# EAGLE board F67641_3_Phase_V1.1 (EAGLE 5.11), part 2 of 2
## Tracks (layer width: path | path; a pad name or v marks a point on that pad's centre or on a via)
ACT  (via drill 0.4)
  Top 0.254: U4.51 117.99,127.26 108.5,136.75 108.5,154.25 100.25,162.5 v59.73,162.5 LED_ACT.K
  Top 0.61: R72.1 v20,160 | JP12.1 34.73,184.77 35,184.5 v35,163.25
  Bottom 0.254: v59.73,162.5 59.73,162.52 59,163.25
  Bottom 0.61: 59,163.25 v35,163.25 33.25,163.25 28.5,158.5 21.5,158.5 v20,160
AUXVCC1  (via drill 0.4)
  Top 0.254: U4.19 115,82.25 116,81.25 116,77.5 116.5,77
  Top 0.406: C5.1 117.25,75.4
  Top 0.61: 116.5,77 C4.1 C5.1 | v117.75,74.25 117.25,74.75 117.25,75.4 | v134.5,74.25 137,76.75 144.69,76.75 JP16.1
  Bottom 0.61: v117.75,74.25 C63.VCC | C63.VCC 131.42,74.25 | C63.VCC v134.5,74.25
AUXVCC2  (via drill 0.4)
  Top 0.254: U4.18 114.49,82.01 115,81.5 115,75.6 C6.1
  Top 0.61: C6.1 C7.1 115.1,72.9 v116.25,71.75 | JP16.3 138,74.25 v135.5,71.75
  Bottom 0.61: v116.25,71.75 v135.5,71.75
AUXVCC3  (via drill 0.4)
  Top 0.254: U4.26 121.01,85.51 v121.5,86 124,86
  Bottom 0.61: v121.5,86 123.25,86 125.5,88.25 133,88.25 133.75,87.5 133.75,82.5 150,66.25 JP15.2
AVCC  (via drill 0.2, 0.6)
  Top 0.254: U4.9 109.99,81.51 110.5,81 110.5,79 111,78.5 111.6,78.5 C31.1 C29.1
  Top 0.406: v85,68.5 D46.C | v85,59 D48.C | v85,78 D44.C
  Top 0.61: D28.C 93.2,31.7 v91.5,30 | D30.C 98.8,31.7 v100.5,30 | D6.C 113.2,31.7 v111.5,30 | D8.C 118.8,31.7 v120.5,30 | D16.C 133.2,31.7 v131.5,30 | D33.C 138.8,31.7 v140.5,30 144,30 145,31 145,50.5 137.5,58 123,58 120,61 113.5,61 112,62.5 112,71 111.5,71.5 111.5,76.75 C29.1 | v85,68.5 R123.1 | v85,78 R117.1 | v85,59 R127.1
  Top 0.813: v91.5,30 88,30 87,31 87,55.5 85,57.5 v85,59 | v85,86 85,87.65 R36.2
  Bottom 0.813: v91.5,30 v100.5,30 v111.5,30 v120.5,30 v131.5,30 v140.5,30 | v85,59 v85,68.5 v85,78 v85,86
BTN1  (via drill 0.2)
  Top 0.406: 132,182 JP1.1 | R49.2 131.4,146.16 BTN1.2
  Top 0.61: v132,163.5 132,182 | v132,158 132,147.26 BTN1.2
  Bottom 0.61: v132,158 v132,163.5
BTN1/RF_VREG_EN  (via drill 0.2)
  Top 0.254: 122.5,146.5 122.5,102.25 124.5,100.25 124.5,94 v124.75,93.75 | U4.37 121.01,90.99 122.25,89.75 v122.25,89.5
  Top 0.61: v129.5,160.5 122.5,153.5 122.5,146.5 | v129.5,166 JP1.2
  Bottom 0.254: v124.75,93.75 124.75,92 v122.25,89.5
  Bottom 0.61: v129.5,160.5 v129.5,166
BTN2  (via drill 0.2)
  Top 0.254: R50.2 125,122 123,120 123,102.5 125,100.5 125,95 v125.5,94.5 | U4.36 120.74,90.51 121.5,89.75 v121.5,89
  Top 0.406: R50.2 131.4,126.05 BTN2.2
  Bottom 0.254: v125.5,94.5 125.5,92 123,89.5 123,89.25 122.5,88.75 121.75,88.75 v121.5,89
COM0  (via drill 0.2)
  Top 0.254: U4.32 116.5,88.5 111.25,93.75 v111.25,94.75
  Bottom 0.254: LCD1.COM0 94.74,150.5 106.5,150.5 113,144 113,96.75 111.25,95 v111.25,94.75
COM1  (via drill 0.2)
  Top 0.254: U4.33 119.61,89 116.75,89 112,93.75 v112,94
  Bottom 0.254: LCD1.COM1 96.78,151 106.75,151 113.5,144.25 113.5,96.5 112,95 v112,94
COM2  (via drill 0.2)
  Top 0.254: U4.34 117,89.5 112.75,93.75 v112.75,94.75
  Bottom 0.254: LCD1.COM2 98.82,151.5 107,151.5 114,144.5 114,96.25 112.75,95 v112.75,94.75
COM3  (via drill 0.2)
  Top 0.254: U4.35 117.25,90 113.5,93.75 v113.5,94
  Bottom 0.254: LCD1.COM3 100.86,152 105.5,152 107.23,152.02 114.5,144.75 114.5,96 113.5,95 v113.5,94
CUR1+
  Top 0.61: 95.25,34.5 95.25,30.75 93.5,29 I1+.TP | 95.25,34.5 95.25,37 | 95.25,37 95.25,40.75 93.95,42.05 TVS2.C 94,43.05 94,44.5 94.45,44.95 R/L9.2 | 95.25,34.5 D3.A | 95.25,37 D11.C
CUR1+1
  Top 0.61: 115.25,34.5 115.25,30.75 113.5,29 I2+.TP | 115.25,34.5 115.25,37 | 115.25,37 115.25,40.75 113.95,42.05 TVS1.C 114,43.05 114,44.5 114.45,44.95 R/L1.2 | 115.25,37 D2.C | 115.25,34.5 D1.A
CUR1+2
  Top 0.61: 135.25,34.5 135.25,30.75 133.5,29 I3+.TP | 135.25,34.5 135.25,37 | 135.25,37 135.25,40.75 133.95,42.05 TVS3.C 134,43.05 134,44.5 134.45,44.95 R/L3.2 | 135.25,37 D14.C | 135.25,34.5 D13.A
CUR1-
  Top 0.61: 96.75,34.5 96.75,30.75 98.5,29 I1-.TP | 96.75,34.5 96.75,37 | 96.75,37 96.75,40.75 98.05,42.05 TVS2.A 98,43.05 98,44.5 97.55,44.95 R/L10.2 | 96.75,37 D12.C | 96.75,34.5 D4.A
CUR1-1
  Top 0.61: 116.75,34.5 116.75,30.75 118.5,29 I2-.TP | 116.75,34.5 116.75,37 | 116.75,37 116.75,40.75 118.05,42.05 TVS1.A 118,43.05 118,44.5 117.55,44.95 R/L2.2 | 116.75,34.5 D5.A | 116.75,37 D10.C
CUR1-2
  Top 0.61: 136.75,34.5 136.75,30.75 138.5,29 I3-.TP | 136.75,34.5 136.75,37 | 136.75,37 136.75,40.75 138.05,42.05 TVS3.A 138,43.05 138,44.5 137.55,44.95 R/L4.2 | 136.75,34.5 D15.A | 136.75,37 D35.C
DB9_+12V
  Top 0.406: D26.1 D25.1 19.88,142.53 22.43,142.53 C55.+ 22.5,137 | R63.2 22.71,134.41 | R63.2 22.5,137 | U1.8 28.09,134.41 26.53,134.41 26.25,134.12 22.52,134.12 R63.2 | Q1.E 22.4,134.2 R63.2 | 22.5,137 C54.2
DB9_-12V  (via drill 0.6)
  Top 0.406: v21.25,140 D24.2 19.7,137.05 C54.1 R67.1 | U1.5 26.66,138.16 26.25,137.75 25.1,137.75 R66.2 25,140 | 25,140 C56.- | v26.5,140 25,140
  Bottom 0.406: v21.25,140 v26.5,140
DB9_GND  (via drill 0.6)
  Top 0.406: U2.3 26.89,143.37 26.5,143.75 26.5,145 26.1,145.4 C56.+ 23.75,145.4 | 23.75,145.4 C55.- | v12,147.5 D27.2 | v23.75,147.38 23.75,145.4
  Bottom 0.406: RS1.G1 6.75,150.5 6.62,150.38
  Bottom 0.61: 2.5,143.5 2.61,143.61 RS1.5 8.18,143.68 v12,147.5 12,150 13,151 21.62,151 23.75,148.88 v23.75,147.38
  Bottom 1.016: RS1.G2 2.5,129.85 2.5,143.5 2.5,146.25 6.62,150.38 6.86,150.61 6.86,150.64
DRESET  (via drill 0.2)
  Top 0.254: U4.100 v107,85.5
  Bottom 0.254: v107,85.5 107,89.5 110,92.5 119.5,92.5 126,99 133.25,99 134.5,100.25 134.5,105.75 136,107.25 138.75,107.25 139.95,108.45 JP5.2
DTCK  (via drill 0.2)
  Top 0.254: U4.99 106.49,85.99 106.75,86.25 v107.75,86.25
  Bottom 0.254: v107.75,86.25 107.75,89.25 110.5,92 119.75,92 126.25,98.5 133.5,98.5 135,100 135,103.5 136,104.5 138.5,104.5 JP6.2
DTDI  (via drill 0.2)
  Top 0.254: U4.97 106,87 106.75,87.75 v109.25,87.75
  Bottom 0.254: v109.25,87.75 109.25,88.75 111.5,91 120.25,91 126.75,97.5 134,97.5 136,99.5 138.5,99.5 139.86,100.86 JP8.2
DTDO  (via drill 0.2)
  Top 0.254: U4.96 105.76,87.51 106.75,88.5 v110,88.5
  Bottom 0.254: v110,88.5 112,90.5 120.5,90.5 127,97 138.5,97 139.82,98.32 JP9.2
DTMS  (via drill 0.2)
  Top 0.254: U4.98 106.25,86.5 106.75,87 v108.5,87
  Bottom 0.254: v108.5,87 108.5,89 111,91.5 120,91.5 126.5,98 133.75,98 135.5,99.75 135.5,101.5 136,102 138.5,102 139.9,103.4 JP7.2
DVCC  (via drill 0.2, 0.4, 0.6)
  Top 0.254: U4.21 115.99,82.76 117.75,81 119.75,81 120.25,80.5 120.25,78.9 C16.1 C17.1 | R41.2 138.4,86.5 | C41.2 143.53,79.38 | IC1.8 141.4,80.38 141.5,80.28 | C51.1 113.5,142.15 R47.1 113.53,144.62 IRDA.P$1 118.62,144.62 118.75,144.75
  Top 0.406: 138.4,86.5 143,86.5 144,85.5 144,80.1 C41.2 142.28,79.5 141.5,80.28 R40.2 | v61,155.5 R58.1 | v71,155.5 R22.1 | v81,155.5 R57.1 | v91,155.5 R21.1 | v101,155.5 R20.1 | v121.25,144.75 118.75,144.75 | JP17.6 118.21,179.04 118.25,179 118.25,168.75 | 117,167.5 118.25,168.75 | 119.5,167.5 118.25,168.75 | 118.25,168.25 118.5,168 | 118.25,168.75 118.25,168.25 | 118.25,168.25 118,168
  Top 0.508: RF1.9 67.97,176.53 68.35,176.15 R79.1
  Top 0.61: R79.1 C59.2 68.35,171 C58.+ 68.6,170.6 68.5,170.5 68.5,168.5 | OPTO2.1 13.98,159.02 17.5,155.5 25.75,155.5 | 43,135.5 R65.1 | 44,136.5 43,135.5 | 44,134.5 43,135.5 | v44,155.5 25.75,155.5 | 67.5,167.5 68.5,168.5 | 69.5,167.5 68.5,168.5 | U2.8 36.2,145.91 R70.2 R71.1 C57.1 39.9,145.85 40,145.75 43,145.75 | 43,145.75 44,144.75 | 44,146.75 43,145.75 | 43,145.75 43.75,145.75 44,145.5 | R19.2 88.15,93.65 88.25,93.75 v88.25,95 | C17.1 120.65,75.85 121.5,75 128,75 135.5,82.5 135.5,86.5 | R51.1 133,95 132.75,94.75 | 135.5,92 135.5,86.5 | R41.2 135.65,86.35 135.5,86.5 | 140.5,142 v139.5,142 R49.1 | 142,143.5 140.5,142 | 142,140.5 140.5,142 | 141,142 141.5,142.5 | 140.5,142 141,142 | 141,142 141.75,141.25 | R50.1 138,122 138.12,121.88 | OPTO1.1 22.23,159.02 25.75,155.5
  Top 0.813: DVCC.1 DVCC.2 154,135.25 154,132.75 DVCC.3 DVCC.4 | R36.1 84.99,94.26 v83.5,95.75
  Top 1.27: JP3.2 73.08,107.92 70,111 55,111 44,122 44,134.5 44,136.5 44,144.75 44,145.5 44,146.75 v44,155.5 56,167.5 67.5,167.5 69.5,167.5 117,167.5 119.5,167.5 125,167.5 142,150.5 142,143.5 142,140.5 142,135 | 142,133 142,135 | 142,133 142,125.75 138.12,121.88 125,108.75 125,102.5 132.75,94.75 135.5,92 142.46,92 JP10.2 | 154,135.25 153.75,135.25 152.5,134 | 154,132.75 153.75,132.75 152.75,133.75 | 152.5,134 152.75,133.75 | 143,134 152.5,134 | 142,135 143,134 | 142,133 143,134 | 152.75,133.75 153.25,133.75 153.75,134.25
  Bottom 0.406: v121.25,144.75 124,142 v139.5,142
  Bottom 0.61: v101,155.5 v91,155.5 v81,155.5 v71,155.5 v61,155.5 v44,155.5 | v88.25,95 87.5,95.75 v83.5,95.75
  Bottom 0.813: JP3.2 73.08,95 73.83,95.75 v83.5,95.75
EXT
  Top 0.813: JP10.3
  Top 1.016: JTAG.4 147.28,95.78 146,94.5 JP10.3
GND  (via drill 0.3, 0.4)
  Top 0.254: v56.5,100 56.5,99.5 U3.9 60.65,99.5 C61.2
  Top 0.406: C61.2 C60.2
  Top 0.61: R44.1 51.5,110 | U2.5 34.41,142.09 35,141.5 36.5,141.5
  Top 0.813: C42.2 65.67,89.35 C101.-
  Top 1.016: D17.A 6,108.5 10,104.5 16.5,104.5 | 16.5,104.5 19,104.5 | 19.5,104.5 28.5,104.5 | 29.5,104.5 31.5,104.5 | 31.5,104.5 34,104.5 36.5,102 36.5,101.96 C102.- 40.96,97.5 | 30,106 31.5,104.5 | 30,106 D21.A | 28.5,104.5 30,106 | 28.5,104.5 29.5,104.5 | 29.5,104.5 30,105 | 16.5,104.5 18,106 | 18,106 D19.A | 18,106 19.5,104.5 | 19,104.5 19.5,104.5 | 19,104.5 18,105.5 | ZD3.A 76,87.95 76.45,87.95 76.5,88 80.5,88 | U$1.VO- 73.85,83.15 74,83 80.5,83
  Top 1.27: L6.2 82,36.5
  Bottom 1.016: C101.- 67.39,89.52 U$1.VO-
  other vias: 125.25,83.25 129,85.25 129,81.25 105,100 84.5,139 72,139 59.5,139 74,171 84.5,132 72,132 59.5,132 102,101.5 106,95.5 106,93.5 108,97.5 119,84.5 119.75,84.5 109,85.75 110.25,87 116,48.5 116,50.5 116,46.5 136,46.5 136,48.5 136,50.5 96,46.5 96,48.5 96,50.5 106,46.5 106,48.5 106,50.5 106,52.5 101,43 103.5,43 106,44.5 108.5,43 111,43 126,46.5 126,48.5 126,50.5 126,52.5 121,43 123.5,43 126,44.5 128.5,43 131,43 141,43 143.5,43 88.5,43 91,43 110,97.5 81,38 81,40 81,42 81,44 81,46 81,48 83,38 83,40 83,42 83,44 83,46 83,48 85,38 85,40 85,42 85,44 85,46 85,48 41,150.5 41,153.5 38,153.5 38,150.5 42,144 42,137.5 42,139.5 42,142 55.5,100 55.5,99 56.5,99 56.5,98 55.5,98 46.5,95 47.5,95 48.5,95 46.5,94 47.5,94 48.5,94 63.25,89.25 62.25,89.25 61.25,89.25 140.25,149.5 140.25,148 140.25,146 140.25,144.5 41,129 41,132 38,132 38,129 89,169.5 89,171.5 86,171.5 86,169.5 94.5,165.5 91.5,165.5
  pour Top: 79.5,108 79.5,36 155.5,36 155.75,169.5 142.5,169.5 142.5,186.5 36,186.5 36,124.5 53,108
  pour Bottom: 79.5,108 79.5,36 155.5,36 155.5,66.5 155.75,169.5 142.5,169.5 142.5,186.5 36,186.5 36,124.5 53,108
  pour Top (no thermals): 53.5,93.5 53.5,95 55,95 55,100.5 54,101.5 54,104.5 57,104.5 57,96.5 58,96.5 58,95.5 57,95.5 57,93.5
  pour Top (no thermals): 41.5,98.75 42.75,97.5 49,97.5 49,95 53.5,95 53.5,93.5 43,93.5 39.5,97 39.5,98 40.25,98.75
  pour Top (no thermals): 64,91.5 57.5,91.5 57,92 57,93.5 43,93.5 44.5,92 52.5,92 56,88.5 64,88.5
  pour Bottom (no thermals): 39.5,98 40.25,98.75 41.5,98.75 42.75,97.5 52,97.5 55,100.5 57,100.5 57,99.75 57.5,99.25 62.5,99.25 64,100.75 64,108 79.5,108 79.5,96.5 58,96.5 57,95.5 57,92 57.5,91.5 64,91.5 64,88.5 56,88.5 52.5,92 44.5,92 39.5,97
I1+_IN
  Top 0.254: U4.1 106.01,74.01 103,71 103,70.5
  Top 0.61: R26.2 94.35,52.4 C19.1 C23.1 97.55,54.55 103,60 103,70.5
I1-_IN
  Top 0.254: U4.2 106.49,72.99 104.5,71 104.5,70.5
  Top 0.61: R27.2 99.45,48.6 C20.1 C23.2 99.45,54.2 104.5,59.25 104.5,70.5
I2+_IN
  Top 0.254: U4.3 107,72 106,71 106,70.5
  Top 0.61: R6.2 114.35,52.4 C2.1 C10.1 117.55,53.95 116.5,55 110.25,55 106,59.25 106,70.5
I2-_IN
  Top 0.254: U4.4 107.5,70.5
  Top 0.61: R7.2 119.35,50.4 C3.1 C10.2 119.45,54.3 117.25,56.5 111,56.5 107.5,60 107.5,70.5
I3+_IN
  Top 0.254: U4.5 108.01,71.99 109,71 109,70.5
  Top 0.61: 137.5,52.5 C11.1 134.35,52.4 R9.2 | 137.5,52.5 C13.1 | 137.5,52.5 137.5,54 136.5,55 121,55 118,58 111.75,58 109,60.75 109,70.5
I3-_IN
  Top 0.254: U4.6 108.5,72.5 110.5,70.5
  Top 0.61: R10.2 139.45,48.6 C12.1 C13.2 139.25,52.7 139.25,54.25 137,56.5 122,56.5 119,59.5 112.5,59.5 110.5,61.5 110.5,70.5
INT
  Top 1.016: JTAG.2 148.24,93.24 144.43,89.43 JP10.1
IR_RXD  (via drill 0.2)
  Top 0.254: U4.27 116.01,85.99 v115.26,86.74 | v120.75,133.25 121.5,132.5 121.5,101.75 123.5,99.75 123.5,93.75 123.25,93.5 v123.25,92.25 | v120.75,146.5 118.39,146.5 IRDA.P$3
  Bottom 0.254: v115.26,86.74 115.25,87.25 115.25,89 116.25,90 120.75,90 123,92.25 v123.25,92.25 | v120.75,133.25 120.5,133.5 120.5,146.25 v120.75,146.5
IR_SD  (via drill 0.2)
  Top 0.254: U4.47 121.25,96 122,96.75 122,99 120,101 120,129 v119.25,129.75 | v120.5,147.5 118.39,147.5 IRDA.P$4
  Bottom 0.254: v119.25,129.75 120.5,131 120.5,132.5 120,133 120,147 v120.5,147.5
IR_TXD  (via drill 0.2)
  Top 0.254: v124,93 124,100 122,102 122,145 121.42,145.57 IRDA.P$2 | U4.28 116.5,86.5 v116.25,86.75
  Bottom 0.254: v116.25,86.75 116,87 116,88.75 116.75,89.5 121,89.5 123,91.5 123.5,91.5 124,92 v124,93
LED_PHASE_1  (via drill 0.2)
  Top 0.254: U4.40 117.51,92.49 v116,94
  Bottom 0.254: v116,94 116,146 99,163 70.25,163 68.02,160.77 LED_PHASE_1.K
LED_PHASE_2  (via drill 0.2)
  Top 0.254: U4.30 115.99,87.51 110,93.5 110,95.25 110.75,96 114,96 115,95 v115,94
  Bottom 0.254: LED_PHASE_2.K 78.02,160.77 79.75,162.5 98.75,162.5 115.5,145.75 115.5,95 115,94.5 v115,94
LED_PHASE_3  (via drill 0.2)
  Top 0.254: U4.31 116.25,88 110.5,93.75 110.5,95 111,95.5 113.5,95.5 v114.25,94.75
  Bottom 0.254: LED_PHASE_3.K 88.02,160.77 89.25,162 98.5,162 115,145.5 115,95.5 v114.25,94.75
LINE_1
  Top 0.813: L1.1 6.92,34.77 R1.2
  Top 1.016: LINE_1.TP 16,18 7,27 7,32.57 R1.2
  Bottom 1.016: R1.2 6.92,40.58 7,63 C39.1
LINE_2
  Top 0.813: L3.1 34.92,34.77 R2.2
  Top 1.016: LINE_2.TP 32,29.73 R2.2
  Bottom 1.016: C46.1 20,47.57 R2.2
LINE_3
  Top 0.813: L5.1 62.92,34.77 R3.2
  Top 1.016: LINE_3.TP 48,17.73 R3.2
  Bottom 1.016: R3.2 56.35,32.65 32,57 C50.1 33.36,65.37 U$1.L
LINE_V1
  Top 0.406: D45.C 85,82 D44.A
  Top 0.813: R101.1 8.65,48.65 15,55 70.5,55 78,62.5 78,76 84,82 85,82 R119.2 | R119.2 R118.2 | R119.2 R116.1
LINE_V2
  Top 0.406: D46.A 85,72.5 D47.C
  Top 0.813: R108.1 36.65,48.65 41,53 71.25,53 80,61.75 80,68.5 84,72.5 85,72.5 R122.2 | R122.2 R121.2 | R122.2 R120.1
LINE_V3
  Top 0.406: D49.C 85,63 D48.A
  Top 0.813: R115.1 64.65,48.65 67,51 72,51 84,63 85,63 R126.2 | R126.2 R125.2 | R126.2 R124.1
N$1
  Top 0.813: U$1.26 43.27,86.31 C100.-
N$2
  Top 0.813: U$1.22 53.44,86.61 C100.+
N$3
  Top 0.61: OPTO2.4 ACT.2
N$4
  Top 0.254: U4.29 121.15,87 C49.1
N$5
  Top 0.254: R20.2 97.4,157.38 LED_REACT.A
N$6
  Top 0.254: R21.2 87.15,157.38 LED_PHASE_3.A
N$7
  Top 0.254: R22.2 67.15,157.38 LED_PHASE_1.A
N$8
  Top 0.61: R6.1 R5.2 112.65,46.6 R/L1.1
N$9
  Top 0.254: U1.2 36.78,135.62 R65.2
N$10
  Top 0.254: JP4.1 138.68,109.75 144.53,109.75 145.06,109.22 R48.2
N$11
  Top 0.61: OPTO2.3 ACT.1
N$12
  Top 0.61: R72.2 16.65,163.06 OPTO2.2
N$13
  Top 0.61: D6.A D1.C
N$14
  Top 0.61: D8.A D5.C
N$15
  Top 0.61: D2.A D7.C
N$16
  Top 0.61: D10.A D9.C
N$17
  Top 0.254: U3.5 53.82,96.17 R38.2
N$18
  Bottom 1.016: D17.C 7.8,97.62 R92.2 8.2,97.62 D18.A
N$19
  Top 0.61: R9.1 R8.2 132.65,46.6 R/L3.1
N$20
  Top 0.61: D28.A D3.C
N$21
  Top 0.61: D16.A D13.C
N$22
  Top 0.254: R69.2 35.75,140 36.5,139.25 37.6,139.25 Q2.B
N$23
  Top 0.61: D11.A D29.C
N$24
  Top 0.406: RS1.2 9.55,136.75 9.8,137 R67.2 15.75,137.35 R64.1
N$25
  Top 0.61: D33.A D15.C
N$26
  Top 0.406: U1.6 29.61,136.88 30,136.5 30,133.5 30,133 29.5,132.5 R62.1
N$27
  Top 0.61: D14.A D32.C
N$28
  Top 0.406: R62.2 22.6,132.5 R63.1 20.45,132.4 Q1.B
N$29
  Top 0.61: D35.A D34.C
N$30
  Bottom 0.254: JP17.2 124.19,179.23 JP1.3
N$32
  Top 0.61: R/L9.1 92.55,48.4 R24.2 R26.1
N$33
  Top 0.406: D37.C 154.2,63.66 JP15.1
N$34
  Top 0.406: D37.A 150.8,59.7 152.21,58.29 HD1.2
N$35
  Top 0.254: RF2.3 97.67,172.72 R74.2
N$37
  Top 0.254: U3.4 52.5,98.5 52,98 C45.1
N$38
  Top 0.254: U3.3 52.25,99 51.25,98 50.35,98 R35.1
  Top 0.406: R37.2 R35.1
N$39
  Top 0.61: D30.A D4.C
N$40
  Top 0.61: D12.A D31.C
N$41
  Top 0.406: Q1.C 15.9,133.25 R64.2
N$43
  Top 0.406: U1.7 26.64,135.62 26.25,136 25.15,136 R66.1
N$44
  Top 0.254: R58.2 57.15,157.38 LED_ACT.A
N$45
  Top 0.254: RF2.5 97.78,174 R76.2
N$46
  Top 0.254: R57.2 77.15,157.38 LED_PHASE_2.A
N$47
  Bottom 1.016: D19.C 19.8,97.62 R93.2 20.2,97.62 D20.A
N$48
  Top 0.254: IRDA.P$5 113.53,148.43 C52.1
  Top 0.3: R47.2 C52.1
N$50
  Top 0.254: R79.2 RF1.7
N$51
  Top 0.254: R73.1 60.99,172.75 RF1.4
N$52
  Top 0.254: RF1.15 66.62,180.34 R87.2
N$53
  Top 0.254: RF1.6 58.48,174 R77.1
N$55
  Top 0.254: RF2.10 88.01,176.53 R83.1
N$56
  Top 0.254: R84.1 91.44,177.75 RF2.12
N$57
  Top 0.254: R85.1 91.45,179.12 RF2.14
N$58
  Top 0.406: 20.17,148.16 D27.1 20.1,147.9 R78.1 28.75,149.75 30,148.5 30,145 29.64,144.63 U2.2
N$59
  Top 0.254: RF2.16 88,180.34 R86.1
N$60
  Top 0.254: RF2.18 88.11,181.62 R88.1
N$61
  Top 0.254: R91.1 89.39,183.25 89.79,182.85 91.47,182.85 RF2.20
N$65
  Top 0.61: OPTO1.4 REACT.2
N$67  (via drill 0.6)
  Top 0.406: v16,149.75 R78.2 | D24.1 10.06,140 RS1.3
  Bottom 0.406: RS1.3 8.18,138.18 10,140 14,140 16,142 v16,149.75
N$68
  Top 0.61: OPTO1.3 REACT.1
N$69
  Top 0.406: D26.2 4,145 2.5,143.5 2.5,138.25 4,136.75 RS1.7
N$71
  Top 0.406: D25.2 9.81,142.5 RS1.4
N$72
  Top 0.61: R68.2 24.9,163.06 OPTO1.2
N$78
  Top 0.254: U3.1 53.25,100 53,100.25 C47.1
N$79
  Top 0.254: U1.3 34.88,136.88 35.3,137.3 Q2.E
N$80  (via drill 0.4)
  other vias: 62,104 62,103 62,102
  pour Top: 57.5,100 57.5,105 53.5,105 53.5,103.5 52.5,103.5 52.5,106 63,106 63,101 59.5,101 59.5,100
  pour Bottom (no thermals): 57.5,100 57.5,105 63,105 63,101 59.5,101 59.5,100
N$81
  Top 0.254: RF1.19 R90.2
N$82
  Top 0.254: R95.1 63.25,96.4
  Top 0.406: 63.25,96.4 C60.1
N$83
  Top 0.254: R89.1 61.01,181.62 RF1.18
N$84
  Bottom 1.016: C39.2 R92.1
N$85
  Top 0.254: RF2.7 97.89,175.26 R80.2
N$86
  Top 0.254: RF2.9 97.81,176.53 R82.2
N$87
  Top 0.254: R81.1 89.81,175 90.04,175.23 91.47,175.23 RF2.8
N$88
  Top 0.254: R75.1 89.19,173.62 89.53,173.96 91.47,173.96 RF2.6
N$89
  Bottom 1.016: C46.2 R93.1
N$90
  Bottom 1.016: C50.2 R94.1
N$92
  Top 0.254: 61.25,96.15 R95.2 | U3.8 59.25,99 60.35,97.9 C61.1
  Top 0.406: C61.1 61.25,96.15
N$93
  Top 0.406: R96.1 R97.2
N$94
  Bottom 1.016: D21.C 31.8,97.62 R94.2 32.2,97.62 D22.A
N$95
  Top 0.254: U3.7 59,98.5 59.5,98 59.5,96.1 R98.2
  Top 0.406: R98.2 R97.1
N$96
  Top 0.813: R4.1 R14.2
N$97
  Top 0.813: R15.2 R14.1
N$98
  Top 0.813: R15.1 R32.2
N$99
  Top 0.813: R32.1 R99.2
N$100
  Top 0.813: R99.1 R100.2
N$101
  Top 0.813: R101.2 R100.1
N$102
  Top 0.813: R102.1 R103.2
N$103
  Top 0.813: R104.2 R103.1
N$104
  Top 0.813: R104.1 R105.2
N$105
  Top 0.813: R105.1 R106.2
N$106
  Top 0.813: R106.1 R107.2
N$107
  Top 0.813: R108.2 R107.1
N$108
  Top 0.813: R109.1 R110.2
N$109
  Top 0.813: R111.2 R110.1
N$110
  Top 0.813: R111.1 R112.2
N$111
  Top 0.813: R112.1 R113.2
N$112
  Top 0.813: R113.1 R114.2
N$113
  Top 0.813: R115.2 R114.1
N$114
  Top 0.813: L1.2 R4.2
N$115
  Top 0.813: L3.2 R102.2
N$116
  Top 0.813: L5.2 R109.2
N$117
  Top 0.813: C9.1 R121.1 R123.2 C36.1
N$118
  Top 0.813: C8.1 R118.1 R117.2 C1.1
N$119
  Top 0.813: R125.1 C38.1 | R127.2 C43.1
  Top 1.016: R127.2 R125.1
NEUTRAL
  Top 1.016: R39.1 58.75,75.75 58.73,75.75 U$1.N
  Top 1.27: L6.1 73.88,30.15 R3.1
  Bottom 1.016: R1.1 17.15,29.35 23.5,23 43.5,23 | 43.5,23 45,23 | 45,23 46.5,23 | 46.5,23 62.5,23 | 62.5,23 64,23 | 64,23 65.5,23 | 65.5,23 67.23,23 R3.1 73.08,36.67 67.5,42.25 48.5,62 48.48,63.5 48.48,65.24 U$1.N | 62.5,23 64,21.5 | 64,21.5 65.5,23 | 64,23 64,21.5 | 64,21.5 NEUTRAL.TP | 43.5,23 45,24.5 | 45,24.5 45,29.5 | 46.5,23 45.08,24.42 R2.1 | 45,23 45,24.5
REACT  (via drill 0.4)
  Top 0.254: U4.52 117.51,126.99 108,136.5 108,154 100,162 98.25,162 | 98.25,162 LED_REACT.K | 98.25,162 61,162 v60.5,161.5
  Top 0.61: R68.1 v28,160 | JP11.1 45.73,184.77 46,184.5 v46,164.5
  Bottom 0.254: v60.5,161.5 60.5,163 59,164.5
  Bottom 0.61: 59,164.5 v46,164.5 32.5,164.5 v28,160
RESET  (via drill 0.2)
  Top 0.254: 133.01,104.75 C53.2 132.89,105.26 | 135,106.5
  Top 0.406: C53.2 R51.2 | 135,106.5 v135,111.5 | C53.2 134.35,105.15 135,105.8 135,106.5 | RESET.1 128.5,106 129.25,105.25 132.9,105.25 C53.2
  Bottom 0.254: 142.27,108.48 JP5.3 | 147.5,104.76 147.49,104.75
  Bottom 0.406: 142.27,108.48 141.25,109.5 141.25,111.75 140.5,112.5 136,112.5 v135,111.5 | JTAG.11 152.01,105.92 150.85,104.76 147.5,104.76 143.77,108.48 JP5.3
RF_CCA  (via drill 0.2, 0.3)
  Top 0.254: 86.03,176.5 86.02,176.5 | U4.41 118,93 v117,94 | v82.25,176.5 86.03,176.5 | 86.03,176.5 R83.2
  Bottom 0.254: v117,94 116.5,94.5 116.5,146.25 100.5,162.25 100.5,169 93,176.5 v82.25,176.5
RF_CLK  (via drill 0.2, 0.3)
  Top 0.254: 86,180.34 R86.2 v82.25,180.5 | U4.46 118.51,95.49 118.25,95.75 v118.25,96.25
  Bottom 0.254: v118.25,96.25 118,96.5 118,147 102,163 102,169.75 91.25,180.5 v82.25,180.5
RF_CS  (via drill 0.2, 0.3)
  Top 0.254: U4.45 v118,95 | v82.25,179 86.03,179 R85.2
  Bottom 0.254: v118,95 117.5,95.5 117.5,146.75 101.5,162.75 101.5,169.5 92,179 v82.25,179
RF_FIFO  (via drill 0.2, 0.3)
  Top 0.254: v103,175.25 R80.1 | v82.25,173.62 R75.2 | v97,170.25 103.25,170.25 105,172 v105,175.25 110.5,180.75 113.02,180.75 JP13.2
  Bottom 0.254: v82.25,173.62 94.38,173.62 95.5,172.5 95.5,171.75 v97,170.25 | v105,175.25 v103,175.25
RF_FIFOP  (via drill 0.2, 0.3)
  Top 0.254: R82.1 99.72,176.5 103.5,176.5 | v82.25,175 R81.2 | v97.25,171 103,171 104,172 104,176 103.5,176.5 | JP14.2 107.77,180.77 103.5,176.5
  Bottom 0.254: v82.25,175 93.75,175 96.25,172.5 96.25,172 v97.25,171
RF_GPIO1  (via drill 0.3, 0.4)
  Top 0.254: U4.49 120.76,97.01 121,97.25 121,98.5 119,100.5 119,127.75 109.5,137.25 109.5,154.75 100.75,163.5 100.75,164 100.25,164.5 99.25,164.5 v99,164.25 | v71,183 68.47,183 R90.1
  Bottom 0.254: v99,164.25 98.75,164 88.5,164 81,171.5 81,180.5 78.5,183 v71,183
RF_GPIO2  (via drill 0.3, 0.4)
  Top 0.254: 56.5,181.47 R89.2 56.52,181.5 v55,181.5 | U4.50 119.61,99.14 118.5,100.25 118.5,127.5 109,137 109,154.5 100,163.5 v99.75,163.5
  Bottom 0.254: v99.75,163.5 88.25,163.5 80.5,171.25 80.5,179.5 78.5,181.5 v55,181.5
RF_RESETCC  (via drill 0.2, 0.3)
  Top 0.254: 68.47,180.25 68.5,180.22 | 68.47,180.5 R87.1 68.47,180.25 | R76.1 99.72,174 v103,174 | U4.48 121,96.5 121.5,97 121.5,98.75 119.5,100.75 119.5,128.25 v118.75,129 | 68.47,180.25 69.25,180.25 70,181 v70,182.25
  Bottom 0.254: v118.75,129 118.5,129.25 118.5,130 120,131.5 120,132.25 119.5,132.75 119.5,147.75 103.5,163.75 103.5,170.5 102,172 | v103,174 102.5,174 102,173.5 102,172 | 102,172 89.5,184.5 71,184.5 70,183.5 v70,182.25
RF_SFD  (via drill 0.2, 0.3)
  Top 0.254: 86.12,177.72 R84.2 v82.25,177.75 | U4.42 118.49,93.51 v118,94
  Bottom 0.254: v118,94 117,95 117,146.5 101,162.5 101,169.25 92.5,177.75 v82.25,177.75
RF_SIMO  (via drill 0.2, 0.3)
  Top 0.254: 85.89,181.62 R88.2 86.03,182 v82.25,182 | U4.44 120.75,94.5 122.5,96.25 122.5,99.25 120.5,101.25 120.5,129.5 v118.75,131.25 116.25,131.25 110,137.5 110,157.5 109.5,158 v109.5,159.5
  Bottom 0.254: v82.25,182 90.5,182 102.5,170 102.5,163.25 118.5,147.25 118.5,131.5 v118.75,131.25 | v109.5,159.5 109.25,159.5 107.5,161.25 107.5,175 111.73,179.23 JP13.1
RF_SOMI  (via drill 0.2, 0.3)
  Top 0.254: 86.11,183.29 R91.2 v82.25,183.25 | U4.43 120.99,93.99 123,96 123,99.5 121,101.5 121,130.25 v119.25,132 116.25,132 110.5,137.75 v110.5,158
  Bottom 0.254: v82.25,183.25 90,183.25 103,170.25 103,163.5 119,147.5 119,132.25 v119.25,132 | v110.5,158 110,158 107,161 107,174.5 105.23,176.27 JP14.1
RF_VREG_EN  (via drill 0.3, 0.4)
  Top 0.254: R74.1 v103,172.5 | v106,173.5 112,179.5 115.94,179.5 JP17.5 JP17.3 JP17.1
  Bottom 0.254: 104,170.75 103,171.75 v103,172.5 105,172.5 v106,173.5
RS232_RXD  (via drill 0.2)
  Top 0.254: U4.16 113.5,87.75 108.5,92.75 108.25,92.75 v107.5,93.5
  Bottom 0.254: v107.5,93.5 112,98 112,121 108.5,124.5 24.73,124.5 RX_EN.2
RS232_TXD  (via drill 0.2)
  Top 0.254: U4.17 114,88 v108.5,93.5
  Bottom 0.254: v108.5,93.5 112.5,97.5 112.5,122 109,125.5 29,125.5 27.25,127.25 24.5,127.25 23.27,128.49 TX_EN.2
S0
  Top 0.254: LCD1.1 51.58,123.16 60.73,114 89,114 92,111 92,95.5 99,88.5 U4.94
S1
  Top 0.254: LCD1.2 54.09,123.16 62.75,114.5 89.25,114.5 92.5,111.25 92.5,95.75 99.25,89 U4.93
S2
  Top 0.254: LCD1.3 56.59,123.16 64.75,115 89.5,115 93,111.5 93,96 99.5,89.5 U4.92
S3
  Top 0.254: LCD1.4 66.75,115.5 89.75,115.5 93.5,111.75 93.5,96.25 99.75,90 U4.91
S4
  Top 0.254: LCD1.5 61.63,123.12 68.75,116 90,116 94,112 94,96.5 100,90.5 U4.90
S5
  Top 0.254: LCD1.6 64.17,123.08 70.75,116.5 90.25,116.5 94.5,112.25 94.5,96.75 100.25,91 U4.89
S6
  Top 0.254: LCD1.7 66.71,123.04 72.75,117 90.5,117 95,112.5 95,97 100.5,91.5 U4.88
S7
  Top 0.254: LCD1.8 69.25,123 74.75,117.5 90.75,117.5 95.5,112.75 95.5,97.25 100.75,92 U4.87
S8
  Top 0.254: LCD1.9 71.79,122.96 76.75,118 91,118 96,113 96,97.5 101,92.5 U4.86
S9
  Top 0.254: LCD1.10 74.33,122.92 78.75,118.5 91.25,118.5 96.5,113.25 96.5,97.75 101.25,93 U4.85
S10
  Top 0.254: LCD1.11 76.87,122.88 80.75,119 91.5,119 97,113.5 97,98 101.5,93.5 U4.84
S11
  Top 0.254: LCD1.12 79.41,122.84 82.75,119.5 91.75,119.5 97.5,113.75 97.5,98.25 101.75,94 U4.83
S12
  Top 0.254: LCD1.13 81.95,122.82 84.75,120 92,120 98,114 98,98.5 102,94.5 U4.82
S13
  Top 0.254: LCD1.14 84.49,122.76 86.75,120.5 92.25,120.5 98.5,114.25 98.5,98.75 102.25,95 U4.81
S14
  Top 0.254: LCD1.15 87.03,122.74 88.75,121 92.5,121 99,114.5 99,99 102.5,95.5 104.37,95.5 U4.80
S15
  Top 0.254: LCD1.16 89.57,122.7 90.75,121.5 92.75,121.5 99.5,114.75 99.5,99.25 102.75,96 U4.79
S16
  Top 0.254: LCD1.17 92.11,122.91 100,115 100,99.5 103,96.5 U4.78
S17
  Top 0.254: LCD1.18 94.65,121.05 100.5,115.25 100.5,99.75 103.24,97.01 U4.77
S18
  Top 0.254: LCD1.19 97.19,119.33 101,115.5 101,100 103.51,97.49 U4.76
S19
  Top 0.254: LCD1.20 99.73,117.54 101.5,115.75 101.5,104.5 102.5,103.5 106.5,103.5 107,103 U4.73
S20
  Top 0.254: LCD1.21 102,122.88 102,104.75 102.75,104 106.75,104 107.5,103.25 U4.72
S21
  Top 0.254: LCD1.22 104.86,123.2 106.81,123.2 107,123 108.01,121.99 U4.71
S22  (via drill 0.2, 0.36)
  Top 0.254: U4.70 108.5,122.5 104,127 v103.5,127 | v103.5,141.5 103.5,151.81 LCD1.23
  Bottom 0.254: v103.5,127 v103.5,141.5
S23  (via drill 0.2, 0.36)
  Top 0.254: v102.5,128 103.75,128 109,122.75 U4.69 | v102.5,142.5 102.5,152.9 LCD1.24
  Bottom 0.254: v102.5,128 v102.5,142.5
S24  (via drill 0.36)
  Top 0.254: v101.5,129 103.5,129 109.51,122.99 U4.68
  Bottom 0.254: v101.5,129 101.5,141 89.57,152.88 LCD1.29
S25  (via drill 0.36)
  Top 0.254: v100.5,130 103.25,130 109.99,123.26 U4.67
  Bottom 0.254: v100.5,130 100.5,141.25 90.25,151.5 88.5,151.5 87.03,152.97 LCD1.30
S26  (via drill 0.36)
  Top 0.254: v99.5,131 103,131 110.5,123.5 U4.66
  Bottom 0.254: v99.5,131 99.5,141.5 90,151 86.5,151 84.49,153.01 LCD1.31
S27  (via drill 0.36)
  Top 0.254: v98.5,132 102.75,132 111.01,123.74 U4.65
  Bottom 0.254: v98.5,132 98.5,141.75 89.75,150.5 84.5,150.5 81.95,153.05 LCD1.32
S28  (via drill 0.36)
  Top 0.254: v97.5,133 102.5,133 111.49,124.01 U4.64
  Bottom 0.254: v97.5,133 97.5,142 89.5,150 82.5,150 79.41,153.09 LCD1.33
S29  (via drill 0.36)
  Top 0.254: v96.5,134 102.25,134 112,124.25 U4.63
  Bottom 0.254: v96.5,134 96.5,142.25 89.25,149.5 80.5,149.5 LCD1.34
S30  (via drill 0.36)
  Top 0.254: v95.5,135 102,135 112.51,124.49 U4.62
  Bottom 0.254: v95.5,135 95.5,142.5 89,149 78.5,149 74.37,153.13 LCD1.35
S31  (via drill 0.36)
  Top 0.254: v94.5,136 101.75,136 112.99,124.76 U4.61
  Bottom 0.254: v94.5,136 94.5,142.75 88.75,148.5 76.5,148.5 71.87,153.13 LCD1.36
S32  (via drill 0.36)
  Top 0.254: v93.5,137 101.5,137 113.5,125 U4.60
  Bottom 0.254: v93.5,137 93.5,143 88.5,148 74.5,148 69.37,153.13 LCD1.37
S33  (via drill 0.36)
  Top 0.254: v92.5,138 101.25,138 114.01,125.24 U4.59
  Bottom 0.254: v92.5,138 92.5,143.25 88.25,147.5 72.5,147.5 66.87,153.13 LCD1.38
S34  (via drill 0.36)
  Top 0.254: v91.5,139 101,139 114.49,125.51 U4.58
  Bottom 0.254: v91.5,139 91.5,143.5 88,147 70.25,147 64.17,153.08 LCD1.39
S35  (via drill 0.36)
  Top 0.254: v90.5,140 100.75,140 115,125.75 U4.57
  Bottom 0.254: v90.5,140 90.5,143.75 87.75,146.5 68.25,146.5 61.63,153.12 LCD1.40
S36  (via drill 0.36)
  Top 0.254: v89.5,141 100.5,141 115.5,126 U4.56
  Bottom 0.254: v89.5,141 89.5,144 87.5,146 66.25,146 59.12,153.13 LCD1.41
S37  (via drill 0.36)
  Top 0.254: v88.5,142 100.25,142 115.99,126.26 U4.55
  Bottom 0.254: v88.5,142 88.5,144.25 87.25,145.5 64.25,145.5 56.62,153.13 LCD1.42
S38  (via drill 0.36)
  Top 0.254: v87.5,143 100,143 116.5,126.5 U4.54
  Bottom 0.254: v87.5,143 87.5,144.5 87,145 62.25,145 54.12,153.13 LCD1.43
S39  (via drill 0.36)
  Top 0.254: v86.5,144 99.75,144 117,126.75 U4.53
  Bottom 0.254: v86.5,144 86,144.5 60,144.5 51.47,153.03 LCD1.44
SCL  (via drill 0.2)
  Top 0.254: U4.38 121.25,91.5 123.5,89.25 125.25,89.25 v126.75,90.75 | IC1.6 139.88,83.89 139.5,83.5 139.5,82.5 139,82 138.28,82 R40.1 137.28,81.97 v137,82.25
  Bottom 0.254: JP2.1 154.02,81.98 154,82 137.25,82 v137,82.25 136.25,83 136.25,88.25 134.25,90.25 127.25,90.25 v126.75,90.75
SDA  (via drill 0.2)
  Top 0.254: U4.39 121.49,92.01 123.75,89.75 124.75,89.75 v125.75,90.75 | IC1.5 139.91,85.16 139.5,84.75 138.35,84.75 R41.1 138.15,84.65 138,84.5 137.25,84.5 v137,84.75
  Bottom 0.254: JP2.2 154.02,84.52 154,84.5 137.25,84.5 v137,84.75 137,88.5 134.75,90.75 127.75,90.75 127,91.5 126.5,91.5 v125.75,90.75
TCK
  Top 0.254: R48.1 145.06,106.47 144.53,105.94 JP6.3
  Bottom 0.254: JP6.3 143.76,105.94 147.57,102.12 150.75,102.12 JTAG.7
TDI
  Bottom 0.254: JP8.3 143.76,100.86 147.62,97 150.79,97 JTAG.3
TDO
  Top 0.254: JP9.3 141.22,99.59 139.31,99.59 138.68,100.22 138.68,107.21 JP5.1
  Bottom 0.254: JP9.3 143.76,98.32 147.57,94.51 150.75,94.51 JTAG.1
TEST/SBWTCK  (via drill 0.2)
  Top 0.254: JTAG.8 147.57,102.77 147.57,111.02 146.3,112.29 143.76,112.29 JP4.3 JP4.2 | U4.95 105.5,88 106.25,88.75 v106.25,89.25
  Bottom 0.254: v106.25,89.25 106.25,89.75 109.5,93 119.25,93 125.75,99.5 133,99.5 134,100.5 134,107.75 136,109.75 138.75,109.75 139.95,110.95 JP4.2
TMS
  Bottom 0.254: JP7.3 143.76,103.4 147.53,99.62 150.71,99.62 JTAG.5
UART_RX  (via drill 0.4)
  Top 0.254: RX_EN.1 28.47,125.97 v33.75,131.25 | U2.6 34.62,143.37 35.4,144.15 R70.1 | R70.1 R71.2 | v36.25,142.5 R70.1
  Bottom 0.254: v36.25,142.5 33.75,140 v33.75,131.25
UART_TX  (via drill 0.4)
  Top 0.254: v32,140 R69.1
  Bottom 0.254: TX_EN.1 29.01,128.51 32,131.5 v32,140
V1_IN  (via drill 0.2, 0.6)
  Top 0.254: U4.11 111.01,84.99 110.75,85.25 v110.25,85.25
  Top 0.813: R116.2 v93.5,84
  Bottom 0.406: v110.25,85.25 109,84 108,84
  Bottom 0.813: v93.5,84 108,84
V2_IN  (via drill 0.2, 0.6)
  Top 0.254: U4.12 111.49,85.26 v110.75,86
  Top 0.813: R120.2 v93.5,74.5
  Bottom 0.406: v110.75,86 111.25,85.5 111.25,84.75 109,82.5
  Bottom 0.813: 109,82.5 101.5,82.5 99.5,80.5 99.5,77 97,74.5 v93.5,74.5
V3_IN  (via drill 0.2, 0.6)
  Top 0.254: U4.13 112,86.25 v111.5,86.75
  Top 0.813: R124.2 v93.5,65
  Bottom 0.406: v111.5,86.75 112.25,86 112.25,84.13 U4.13 109.12,81
  Bottom 0.813: v93.5,65 97,65 102,70 102,80 103,81 109.12,81
VASYS
  Top 0.254: 110.5,82.5 U4.10 | 110.5,82.5 | C28.1 C32.1 111,81.5 110.5,82 110.5,82.5
VCC_ISO
  Top 1.016: U$1.VO+ 65.5,86.33 C101.+ 65.67,87.65 C42.1 71.6,87.65 ZD3.C 71.95,89.45 73,90.5 74.5,90.5 75.62,91.62 JP3.1
VCC_PL  (via drill 0.4)
  other vias: 64.25,94.25 64.25,93.25 65.25,94.25 65.25,93.25
  pour Top (no thermals): 59,93.25 60.75,93.25 60.75,94.75 71.5,94.75 71.5,92.5 59,92.5
  pour Bottom (no thermals): 57.5,94.75 57.5,92.5 71.5,92.5 71.5,94.75
VCORE
  Top 0.254: U4.23 117,82.5 118,81.5 120,81.5 121.5,80 C33.1
VDSYS  (via drill 0.2)
  Top 0.254: C15.1 C14.1 117,80.15 117,81 115.5,82.5 U4.20 115.5,85 v115,85.5 114.5,86 114.5,88.25 109.25,93.5 109.25,94.25 103,100.5 103,102 103.5,102.5 105,102.5 105.85,101.65 C18.1 106.49,100.86 U4.74
  Bottom 0.61: v115,85.5 117.5,85.5 119.5,87.5 123,87.5 125,89.5 133.5,89.5 135,88 135,83 149.21,68.79 JP15.3
VREF
  Top 0.254: C30.1 109.5,81 109,81.5 U4.7
VSENSE  (via drill 0.2, 0.4)
  Top 0.254: U4.15 112.99,86.99 113,87.5 108.25,92.25 v107.75,92.25 | v92.75,93.5 91.5,94.75 91.5,110.75 88.75,113.5 v56,113.5
  Top 0.61: 46,110 v46,112 | R45.1 46,110 | 46,110 R44.2
  Bottom 0.254: v107.75,92.25 94,92.25 v92.75,93.5
  Bottom 0.61: v56,113.5 47.5,113.5 v46,112
VSUPPLY
  Top 0.254: U3.2 50.35,99.5 R35.2
  Top 0.61: 41,110 R45.2
  Top 1.016: D18.C 10,111 13.5,114.5 20.5,114.5 | 20.5,114.5 23,114.5 | 23.5,114.5 32.5,114.5 | 20.5,114.5 22,112.5 | 22,112.5 D20.C | 22,112.5 23.5,114.5 | 23,114.5 23.5,114.5 | 23,114.5 21.5,113.5 | 34,113 35.5,114.5 | 34,113 D22.C | 32.5,114.5 34,113 | 32.5,114.5 33,114.5 | 33,114.5 35.5,114.5 | 33,114.5 34,113.5 | 35.5,114.5 36.5,114.5 41,110 C102.+
  pour Top (no thermals): 52,99 52,100.25 45,100.25 41,104.25 40,103.5 39.75,103.25 39.75,102.25 43.5,98.5 48.75,98.5 48.75,99
VTEMP  (via drill 0.2, 0.4)
  Top 0.254: U4.14 112.51,87.24 108.25,91.5 v107,91.5
  Top 0.406: v94.5,91.5 RTH.2 R19.1
  Bottom 0.406: v94.5,91.5 v107,91.5
XIN
  Top 0.254: 125.9,80.6 C37.1 125.9,81.1 125,82 XT1.P2 122.9,82.15 121.35,82.15 120.5,83 119.75,83 119,82.25 118,82.25 117.51,82.74 U4.24
XOUT
  Top 0.254: XT1.P1 122.9,84.69 | XT1.P1 121.5,84.5 120.5,83.5 119.5,83.5 118.75,82.75 118.25,82.75 117.99,83.01 U4.25 | XT1.P1 125.05,84.5 125.86,85.31 125.86,85.96 C40.1

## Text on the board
Dimension: C:/Documents and Settings/a0272391/Desktop/warning-sign.bmp
tPlace: + | + | + | + | + | Danger | Danger | High Voltage | High Voltage | 50 mA MAX | 50 mA MAX | 50 mA MAX | 120/240 Vrms | 120/240 Vrms | 120/240 Vrms | 50/60 Hz | 50/60 Hz | 50/60 Hz
tNames: REACT | RF_VREG_EN | ACT | DGND | DGND | RF_SOMI | RF_FIFOP | RF_SIMO | RF_FIFO | RF_VREG_EN | MSP430 | BTN1 | ISOLATED | DVCC | GND | MSP430 | ACTIVE | PHASE 1 | PHASE 2 | PHASE 3 | REACTIVE | 1 | + | + | 1 | RS232 | S=SBW | S | J | J=JTAG | DVCC | VCC_PL | VCC_ISO | EXTERNAL | INTERNAL | DVCC | SDA | SCL | AUXVCC1 | AUXVCC2 | DGND | VDSYS | AUXVCC3 | DIODE | VBAT | DGND | M. THRUN / JUNE 2013 | MSP430F67641 3-Phase Energy Meter | Version 1.1
_tplace: JP1 | REACT | R90 | R91 | JP14 | JP13 | RF_VREG_EN | ACT | DGND | DGND | R89 | R88 | ACT | REACT | R87 | R86 | R85 | RF_SOMI | RF_FIFOP | RF_SIMO | RF_FIFO | RF_VREG_EN | MSP430 | BTN1 | R84 | ISOLATED | R83 | DVCC | GND | MSP430 | R82 | R77 | R79 | R81 | R80 | R75 | R73 | C59 | R76 | R74 | 1 | 1 | C58 | RF1 | RF2 | JP17 | OPTO2 | OPTO1 | ACTIVE | PHASE 1 | PHASE 2 | PHASE 3 | REACTIVE | R72 | R68 | + | + | + | + | + | DGND | RS1 | R58 | R22 | R57 | R21 | R20 | IRDA | BTN1 | R78 | D27 | C52 | C55 | C56 | 1 | U2 | R70 | R71 | C57 | + | D26 | 5 | R47 | 9 | D25 | + | R69 | 4 | D24 | R49 | 8 | C51 | 3 | U1 | Q2 | R67 | C54 | 7 | 2 | R66 | Q1 | R65 | 6 | R63 | 1 | R64 | 1 | R62 | BTN2 | DVCC | TX_EN | RX_EN | LCD1 | RS232 | R50 | JTAG | S=SBW | S | J | R45 | R44 | J=JTAG | C53 | DVCC | R48 | D23 | D17 | D18 | D19 | D20 | D21 | D22 | C18 | R51 | C47 | * | C61 | C60 | 14 | RESET | R35 | U3 | C48 | R98 | R95 | VCC_PL | VCC_ISO | R97 | EXTERNAL | R19 | R37 | C45 | R38 | R96 | JP3 | RTH | C62 | INTERNAL | 2 | 1 | ZD3 | C49 | DVCC | U4 | R39 | C42 | R36 | C40 | R41 | IC1 | SDA | R92 | R93 | R94 | D45 | R116 | SCL | XT1 | R40 | R119 | 26 | 22 | VO+ | VO- | C41 | D44 | R118 | C8 | C37 | C30 | R117 | C1 | AUXVCC1 | C32 | C28 | C33 | AUXVCC2 | R120 | C31 | C14 | C16 | D47 | C29 | C6 | C15 | C17 | DGND | R122 | C4 | C7 | C5 | JP15 | R121 | C9 | D46 | VDSYS | R123 | C36 | L | N | NC | AUXVCC3 | R124 | D49 | DIODE | R126 | C39 | C46 | C50 | R125 | C38 | D37 | D48 | R127 | C43 | VBAT | Danger | Danger | DGND | HD1 | C19 | C2 | C11 | High Voltage | High Voltage | C23 | C10 | C13 | R26 | R6 | R9 | C20 | C3 | C12 | M. THRUN / JUNE 2013 | R24 | R5 | R8 | R27 | R7 | R10 | R101 | R100 | R108 | R107 | R115 | R114 | R/L9 | R/L1 | R/L3 | R/L10 | R/L2 | R/L4 | R32 | R105 | R112 | TVS2 | TVS1 | TVS3 | R99 | R106 | R113 | R15 | R14 | R104 | R103 | R111 | R110 | D29 | D7 | D32 | D31 | D9 | D34 | L1 | L3 | L5 | D11 | D12 | D2 | D10 | D14 | D35 | R4 | R102 | R109 | D3 | D1 | D13 | R1 | R2 | R3 | D4 | D5 | D15 | D28 | D30 | D6 | D8 | D16 | D33 | L6 | I1+ | I1- | I2+ | I2- | I3+ | I3- | 50 mA MAX | 50 mA MAX | 50 mA MAX | LINE_1 | LINE_2 | LINE_3 | NEUTRAL | 120/240 Vrms | 120/240 Vrms | 120/240 Vrms | 50/60 Hz | 50/60 Hz | 50/60 Hz | MSP430F67641 3-Phase Energy Meter | Version 1.1
_bplace: C102 | L7 | C100 | C101 | + | - | C63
